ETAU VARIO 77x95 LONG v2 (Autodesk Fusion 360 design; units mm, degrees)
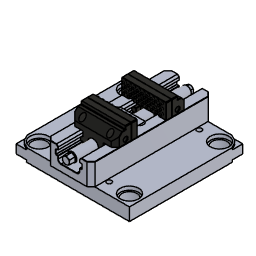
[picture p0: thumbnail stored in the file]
parameter "Ouverture" = 50
base_feature "Base Feature1"
joint_origin "JointOrigin1" OffsetX 0 OffsetY 0 OffsetZ 0
base_feature "Base Feature1"
base_feature "Base Feature1"
base_feature "Base Feature1"
joint_origin "JointOrigin1" OffsetX 0 OffsetY 0 OffsetZ 0
base_feature "Base Feature1"
base_feature "Base Feature1"
base_feature "Base Feature1"
base_feature "Base Feature1"
base_feature "Base Feature1"
base_feature "Base Feature1"
as_built_joint "As-built1"
ground "Ground1"
as_built_joint "As-built1"
as_built_joint "As-built1"
as_built_joint "As-built2"
joint "Assemble1" alignOffsetX 0 alignOffsetY 0 alignOffsetZ 25 (= "Ouverture / 2")
joint "Assemble2" alignOffsetX 0 alignOffsetY 0 alignOffsetZ 25 (= "Ouverture / 2")
position "Position1"
position "Position3" TranslateAlongZ 0
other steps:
create_component "CreateComponent1"
create_component "CreateComponent1"
create_component "CreateComponent2"
create_component "CreateComponent2"
create_component "CreateComponent1"
create_component "CreateComponent2"
create_component "CreateComponent3"
create_component "CreateComponent1"
create_component "CreateComponent2"
create_component "CreateComponent3"
create_component "CreateComponent4"
joint_origin "JointOrigin1" OffsetX 0 OffsetY 0 OffsetZ 0
joint_origin "JointOrigin2" OffsetX 0 OffsetY 0 OffsetZ 0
